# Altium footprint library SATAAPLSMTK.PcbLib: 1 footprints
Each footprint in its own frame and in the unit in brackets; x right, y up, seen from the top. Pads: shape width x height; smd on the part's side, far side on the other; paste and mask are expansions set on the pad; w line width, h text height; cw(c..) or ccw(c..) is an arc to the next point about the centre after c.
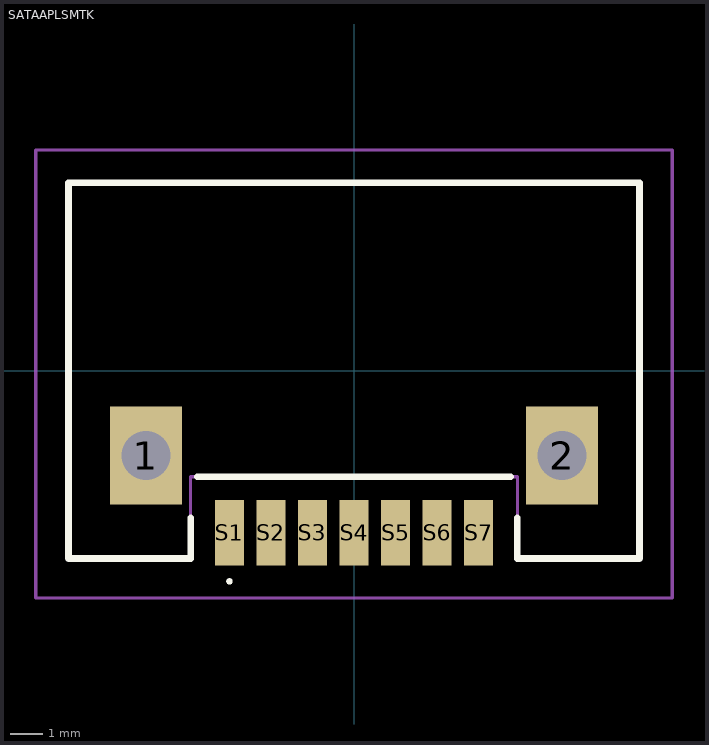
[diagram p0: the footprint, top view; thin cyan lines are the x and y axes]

## SATAAPLSMTK [mm]
pads (9):
  rect 2.2x3 hole 1.5: 1(-6.37,-2.6) 2(6.37,-2.6)
  rect 0.9x2 smd: S1(-3.81,-4.96) S2(-2.54,-4.96) S3(-1.27,-4.96) S4(0,-4.96) S5(1.27,-4.96) S6(2.54,-4.96) S7(3.81,-4.96)
Top Overlay:
  lines w0.1: -3.81,-6.5 -3.81,-6.5 ; -3.81,-6.5 ccw(c-3.81,-6.45) -3.81,-6.4 ; -3.81,-6.5 cw(c-3.81,-6.45) -3.81,-6.4 ; -3.81,-6.4 -3.81,-6.4
  lines w0.2: -5,-4.505 -5,-5.75 -8.735,-5.75 -8.735,5.75 8.735,5.75 8.735,-5.75 5,-5.75 5,-4.505 ; -4.8,-3.25 4.8,-3.25
Mechanical 15:
  lines w0.1: -8.735,-5.75 -5,-5.75 -5,-3.25 5,-3.25 5,-5.75 8.735,-5.75 8.735,5.75 0,5.75 -8.735,5.75 -8.735,-5.75
Mechanical 20:
  lines w0.1: -9.735,-6.96 9.735,-6.96 9.735,6.75 -9.735,6.75 -9.735,-6.96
